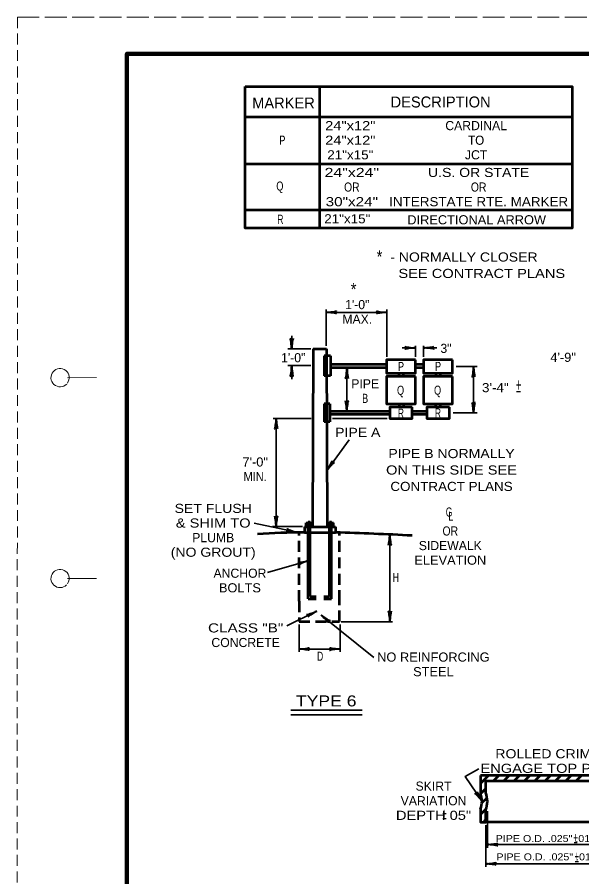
# Model space of a CAD drawing. Extents: x -209 to 471, y -242 to 199.
# Drawn here: x -208.7 to -54, y -37 to 198.5 of the extents above; entities that cross this region are included whole.
import ezdxf
from ezdxf.enums import TextEntityAlignment as Align

# ---------------------------------------------------------------- set-up
doc = ezdxf.new("R2010")
doc.units = 0
doc.linetypes.add('LONG_DASHED', pattern=[7.5, 6, -1.5])
doc.linetypes.add('MEDIUM_DASHED', pattern=[4.5, 3, -1.5])
doc.layers.add('1', color=7, linetype='Continuous', lineweight=53)
doc.layers.add('61', color=7, linetype='Continuous', lineweight=35)

msp = doc.modelspace()

# ---------------------------------------------------------------- linework, layer by layer
at = {"layer": '1', "linetype": 'MEDIUM_DASHED', "lineweight": 13}
msp.add_line((-208.646, 198.515), (-208.706, -241.525), dxfattribs=at)
at = {"layer": '1'}
for p, q in [((-125.758, 140.697), (-125.758, 179.502)), ((-146.273, 171.208), (-56.667, 171.208)), ((-146.273, 158.332), (-56.667, 158.332)), ((-146.273, 145.777), (-56.667, 145.777)), ((-127.607, 107.697), (-127.742, 58.912)), ((-127.607, 107.697), (-123.953, 107.697)), ((-123.953, 107.697), (-123.751, 58.912)), ((-122.877, 105.734), (-124.623, 105.734)), ((-124.623, 105.734), (-124.623, 100.233)), ((-122.877, 105.734), (-122.877, 100.233)), ((-107.531, 103.394), (-122.877, 103.394)), ((-107.531, 102.464), (-122.877, 102.464)), ((-97.371, 103.358), (-99.585, 103.358)), ((-97.371, 102.502), (-99.585, 102.502)), ((-122.877, 100.233), (-124.623, 100.233)), ((-104.015, 100.077), (-104.015, 101.011)), ((-102.83, 100.077), (-102.83, 101.011)), ((-93.855, 100.077), (-93.855, 101.011)), ((-92.67, 100.077), (-92.67, 101.011)), ((-123.036, 92.643), (-124.623, 92.643)), ((-124.623, 92.643), (-124.623, 87.642)), ((-123.036, 92.643), (-123.036, 87.642)), ((-104.015, 92.597), (-104.015, 91.661)), ((-102.83, 92.597), (-102.83, 91.661)), ((-93.988, 91.661), (-93.988, 92.597)), ((-92.697, 91.661), (-92.697, 92.597)), ((-106.595, 90.516), (-123.036, 90.516)), ((-106.595, 89.671), (-123.036, 89.671)), ((-96.435, 90.516), (-100.426, 90.516)), ((-96.435, 89.671), (-100.425, 89.671)), ((-123.036, 87.642), (-124.623, 87.642)), ((-130.005, 58.912), (-121.489, 58.912)), ((-130.005, 58.912), (-130.005, 57.361)), ((-129.473, 58.912), (-129.473, 59.977)), ((-129.473, 59.977), (-127.875, 59.977)), ((-129.02, 59.977), (-129.02, 60.056)), ((-129.02, 60.056), (-128.328, 60.056)), ((-128.94, 60.243), (-128.408, 60.243)), ((-128.94, 60.056), (-128.94, 60.243)), ((-128.94, 39.217), (-128.94, 59.977)), ((-128.408, 60.056), (-128.408, 60.243)), ((-128.408, 39.823), (-128.408, 59.977)), ((-128.328, 59.977), (-128.328, 60.056)), ((-127.875, 58.912), (-127.875, 59.977)), ((-123.618, 59.977), (-122.021, 59.977)), ((-123.618, 58.912), (-123.618, 59.977)), ((-123.166, 59.977), (-123.166, 60.056)), ((-123.166, 60.056), (-122.474, 60.056)), ((-123.086, 60.243), (-122.554, 60.243)), ((-123.086, 60.056), (-123.086, 60.243)), ((-123.086, 39.823), (-123.086, 59.977)), ((-122.554, 60.056), (-122.554, 60.243)), ((-122.554, 39.217), (-122.554, 59.977)), ((-122.474, 59.977), (-122.474, 60.056)), ((-122.021, 58.912), (-122.021, 59.977)), ((-121.489, 58.912), (-121.489, 57.361)), ((-130.005, 57.361), (-121.489, 57.361)), ((-128.94, 39.217), (-126.811, 39.217)), ((-128.408, 39.823), (-126.811, 39.823)), ((-124.681, 39.823), (-123.086, 39.823)), ((-124.681, 39.217), (-122.554, 39.217)), ((-81.745, -9.195), (-81.745, -14.242)), ((-81.745, -11.425), (-79.515, -9.195)), ((-78.151, -10.659), (-76.687, -9.195)), ((-75.322, -10.659), (-73.858, -9.195)), ((-72.494, -10.659), (-71.03, -9.195)), ((-69.665, -10.659), (-68.201, -9.195)), ((-66.837, -10.659), (-65.373, -9.195)), ((-64.009, -10.659), (-62.544, -9.195)), ((-61.18, -10.659), (-59.716, -9.195)), ((-58.352, -10.659), (-56.888, -9.195)), ((-55.523, -10.659), (-54.059, -9.195)), ((-81.742, -14.251), (-80.281, -12.79)), ((-81.359, -16.697), (-79.957, -15.294)), ((-81.745, -19.911), (-80.201, -18.366)), ((-80.963, -21.957), (-80.281, -21.275)), ((-46.185, -21.957), (-80.281, -21.957))]:
    msp.add_line(p, q, dxfattribs=at)
at = {"layer": '1', "lineweight": 35}
for p, q in [((-124.04, 108.496), (-124.04, 118.454)), ((-107.42, 105.457), (-107.42, 118.454)), ((-107.42, 117.655), (-124.04, 117.655)), ((-133.476, 111.224), (-133.476, 107.594)), ((-99.585, 105.457), (-99.585, 108.465)), ((-97.371, 105.457), (-97.371, 108.465)), ((-128.275, 107.697), (-134.506, 107.697)), ((-99.585, 107.935), (-103.215, 107.935)), ((-93.741, 107.935), (-97.371, 107.935)), ((-128.275, 103.095), (-134.506, 103.095)), ((-133.476, 102.996), (-133.476, 99.366)), ((-118.36, 102.464), (-118.36, 90.516)), ((-88.425, 102.835), (-82.646, 102.835)), ((-83.646, 102.835), (-83.646, 90.118)), ((-89.266, 90.118), (-82.646, 90.118)), ((-128.187, 88.596), (-138.514, 88.596)), ((-137.736, 88.596), (-137.736, 58.954)), ((-107.327, 88.596), (-122.31, 88.596)), ((-123.793, 74.388), (-117.719, 82.778)), ((-132.043, 57.415), (-143.764, 59.901)), ((-130.545, 58.954), (-138.705, 58.954)), ((-106.585, 32.92), (-106.585, 56.801)), ((-128.94, 49.597), (-140.112, 46.417)), ((-126.643, 35.808), (-134.791, 31.772)), ((-125.403, 34.721), (-110.972, 23.157)), ((-131.461, 32.148), (-131.461, 24.7)), ((-120.22, 32.126), (-120.22, 24.679)), ((-119.891, 32.92), (-105.859, 32.92)), ((-131.461, 25.427), (-120.22, 25.427)), ((-133.729, 8.726), (-114.169, 8.726)), ((-133.729, 7.361), (-114.169, 7.361)), ((-79.864, -18.944), (-79.864, -28.988)), ((-80.281, -22.836), (-80.281, -34.273)), ((-79.864, -28.109), (-46.599, -28.109)), ((-80.281, -33.395), (-46.185, -33.395))]:
    msp.add_line(p, q, dxfattribs=at)
at = {"layer": '1', "linetype": 'MEDIUM_DASHED'}
for p, q in [((-131.473, 38.541), (-131.473, 57.345)), ((-120.36, 38.541), (-120.36, 57.326))]:
    msp.add_line(p, q, dxfattribs=at)
at = {"layer": '1'}
for points in [[(-146.273, 179.502), (-56.667, 179.502), (-56.667, 140.697), (-146.273, 140.697)], [(-99.585, 104.658), (-107.531, 104.658), (-107.531, 101.011), (-99.585, 101.011)], [(-89.425, 104.658), (-97.371, 104.658), (-97.371, 101.011), (-89.425, 101.011)], [(-99.585, 100.077), (-107.531, 100.077), (-107.531, 92.597), (-99.585, 92.597)], [(-89.425, 100.077), (-97.371, 100.077), (-97.371, 92.597), (-89.425, 92.597)], [(-100.426, 91.661), (-106.595, 91.661), (-106.595, 88.575), (-100.426, 88.575)], [(-90.266, 91.661), (-96.435, 91.661), (-96.435, 88.575), (-90.266, 88.575)]]:
    msp.add_lwpolyline(points, close=True, dxfattribs=at)
at = {"layer": '1', "linetype": 'MEDIUM_DASHED'}
msp.add_lwpolyline([(-131.473, 38.541), (-131.473, 32.948), (-120.36, 32.948), (-120.36, 38.541)], dxfattribs=at)
msp.add_lwpolyline([(-131.473, 38.541), (-131.473, 32.948), (-120.36, 32.948), (-120.36, 38.541)], dxfattribs=at)
at = {"layer": '1', "lineweight": 35}
msp.add_lwpolyline([(-81.328, -16.308), (-85.959, -9.53), (-82.231, -7.366)], dxfattribs=at)
at = {"layer": '1'}
for points in [[(-44.721, -14.248), (-44.721, -9.195), (-81.745, -9.195)], [(-80.281, -13.966), (-80.281, -10.659), (-46.185, -10.659), (-46.185, -13.973)], [(-81.745, -18.375), (-81.745, -21.957), (-80.281, -21.957), (-80.281, -18.651)]]:
    msp.add_lwpolyline(points, dxfattribs=at)
for centre, radius, start, end in [((-127.954, -189.648), 247.017, 90.47573, 93.46734), ((-154.039, -1008.148), 1066.006, 87.12083, 88.25023), ((-86.666, -16.308), 6.801, 339.85367, 20.14633), ((-86.666, -16.308), 5.337, 337.22508, 22.77492)]:
    msp.add_arc(centre, radius, start, end, dxfattribs=at)
at = {"layer": '1', "lineweight": 40}
for centre, major_axis, ratio, start_param, end_param in [((-122.919, 117.867), (-1.756, -0.176), 0.07063, 0.8650754, 3.1424706), ((-108.511, 117.932), (1.786, -0.156), 0.122415, 3.1415927, 5.386832), ((-108.511, 117.932), (1.786, -0.156), 0.122415, 3.1415927, 5.386832), ((-122.949, 117.379), (-1.786, 0.156), 0.122415, 3.1415927, 5.386832), ((-108.541, 117.444), (1.756, 0.176), 0.07063, 0.8650754, 3.1424706), ((-108.541, 117.444), (1.756, 0.176), 0.07063, 0.8650754, 3.1424706), ((-133.688, 108.714), (0.176, -1.756), 0.07063, 0.8650754, 3.1424706), ((-133.2, 108.685), (-0.156, -1.786), 0.122415, 3.1415927, 5.386832), ((-100.676, 108.211), (1.786, -0.156), 0.122415, 3.1415927, 5.386832), ((-96.25, 108.146), (-1.756, -0.176), 0.07063, 0.8650754, 3.1424706), ((-100.705, 107.723), (1.756, 0.176), 0.07063, 0.8650754, 3.1424706), ((-96.28, 107.658), (-1.786, 0.156), 0.122415, 3.1415927, 5.386832), ((-133.752, 101.904), (0.156, 1.786), 0.122415, 3.1415927, 5.386832), ((-133.264, 101.875), (-0.176, 1.756), 0.07063, 0.8650754, 3.1424706), ((-118.628, 101.364), (0.156, 1.786), 0.122415, 3.1415927, 5.386832), ((-118.14, 101.335), (-0.176, 1.756), 0.07063, 0.8650754, 3.1424706), ((-83.923, 101.743), (0.156, 1.786), 0.122415, 3.1415927, 5.386832), ((-83.435, 101.714), (-0.176, 1.756), 0.07063, 0.8650754, 3.1424706), ((-118.58, 91.645), (0.176, -1.756), 0.07063, 0.8650754, 3.1424706), ((-118.092, 91.616), (-0.156, -1.786), 0.122415, 3.1415927, 5.386832), ((-83.858, 91.239), (0.176, -1.756), 0.07063, 0.8650754, 3.1424706), ((-83.37, 91.209), (-0.156, -1.786), 0.122415, 3.1415927, 5.386832), ((-138.012, 87.505), (0.156, 1.786), 0.122415, 3.1415927, 5.386832), ((-137.524, 87.475), (-0.176, 1.756), 0.07063, 0.8650754, 3.1424706), ((-123.307, 75.42), (-0.888, -1.526), 0.07063, 0.8650754, 3.1424706), ((-122.929, 75.11), (-1.174, -1.355), 0.122415, 3.1415927, 5.386832), ((-137.947, 60.075), (0.176, -1.756), 0.07063, 0.8650754, 3.1424706), ((-137.947, 60.075), (0.176, -1.756), 0.07063, 0.8650754, 3.1424706), ((-137.459, 60.046), (-0.156, -1.786), 0.122415, 3.1415927, 5.386832), ((-137.459, 60.046), (-0.156, -1.786), 0.122415, 3.1415927, 5.386832), ((-133.168, 57.371), (1.779, -0.218), 0.122415, 0.8963533, 3.1415927), ((-133.095, 57.854), (1.682, -0.536), 0.07063, 3.1407148, 5.41811), ((-106.797, 55.681), (0.176, 1.756), 0.07063, 3.1407148, 5.41811), ((-106.309, 55.71), (-0.156, 1.786), 0.122415, 0.8963533, 3.1415927), ((-130.076, 49.494), (1.737, 0.312), 0.07063, 3.1407148, 5.41811), ((-129.914, 49.032), (1.675, 0.639), 0.122415, 0.8963533, 3.1415927), ((-127.741, 35.5), (1.652, 0.622), 0.07063, 3.1407148, 5.41811), ((-127.741, 35.5), (1.652, 0.622), 0.07063, 3.1407148, 5.41811), ((-127.499, 35.076), (1.531, 0.932), 0.122415, 0.8963533, 3.1415927), ((-127.499, 35.076), (1.531, 0.932), 0.122415, 0.8963533, 3.1415927), ((-106.861, 34.011), (0.156, -1.786), 0.122415, 0.8963533, 3.1415927), ((-106.374, 34.04), (-0.176, -1.756), 0.07063, 3.1407148, 5.41811), ((-124.661, 33.855), (-1.261, 1.235), 0.07063, 3.1407148, 5.41811), ((-124.379, 34.254), (-1.491, 0.995), 0.122415, 0.8963533, 3.1415927), ((-130.341, 25.215), (-1.756, 0.176), 0.07063, 3.1407148, 5.41811), ((-130.341, 25.215), (-1.756, 0.176), 0.07063, 3.1407148, 5.41811), ((-130.37, 25.703), (-1.786, -0.156), 0.122415, 0.8963533, 3.1415927), ((-130.37, 25.703), (-1.786, -0.156), 0.122415, 0.8963533, 3.1415927), ((-121.311, 25.15), (1.786, 0.156), 0.122415, 0.8963533, 3.1415927), ((-121.311, 25.15), (1.786, 0.156), 0.122415, 0.8963533, 3.1415927), ((-121.341, 25.638), (1.756, -0.176), 0.07063, 3.1407148, 5.41811), ((-121.341, 25.638), (1.756, -0.176), 0.07063, 3.1407148, 5.41811), ((-82.172, -15.563), (1.136, -1.386), 0.122415, 0.8963533, 3.1415927), ((-82.172, -15.563), (1.136, -1.386), 0.122415, 0.8963533, 3.1415927), ((-81.785, -15.264), (0.846, -1.549), 0.07063, 3.1407148, 5.41811), ((-81.785, -15.264), (0.846, -1.549), 0.07063, 3.1407148, 5.41811), ((-78.773, -27.833), (-1.786, -0.156), 0.122415, 0.8963533, 3.1415927), ((-78.773, -27.833), (-1.786, -0.156), 0.122415, 0.8963533, 3.1415927), ((-78.743, -28.321), (-1.756, 0.176), 0.07063, 3.1407148, 5.41811), ((-78.743, -28.321), (-1.756, 0.176), 0.07063, 3.1407148, 5.41811), ((-79.19, -33.118), (-1.786, -0.156), 0.122415, 0.8963533, 3.1415927), ((-79.19, -33.118), (-1.786, -0.156), 0.122415, 0.8963533, 3.1415927), ((-79.161, -33.606), (-1.756, 0.176), 0.07063, 3.1407148, 5.41811), ((-79.161, -33.606), (-1.756, 0.176), 0.07063, 3.1407148, 5.41811)]:
    msp.add_ellipse(centre, major_axis=major_axis, ratio=ratio, start_param=start_param, end_param=end_param, dxfattribs=at)
at = {"layer": '61', "linetype": 'LONG_DASHED', "lineweight": 13}
msp.add_line((-208.646, 198.515), (471.374, 198.515), dxfattribs=at)
at = {"layer": '61', "lineweight": 13}
for p, q in [((-194.926, 99.755), (-186.946, 99.775)), ((-194.946, 44.755), (-186.946, 44.755))]:
    msp.add_line(p, q, dxfattribs=at)
at = {"layer": '61', "lineweight": 158}
msp.add_lwpolyline([(460.394, 188.515), (-178.646, 188.515), (-178.646, -231.505)], dxfattribs=at)
at = {"layer": '61', "lineweight": 13}
for centre, end in [((-196.948, 99.756), 316.23216), ((-196.948, 44.756), 315.37577)]:
    msp.add_arc(centre, 2.5, 323.13009, end, dxfattribs=at)

# ---------------------------------------------------------------- texts
at = {"layer": '1'}
for s, p in [('DESCRIPTION', (-106.384, 173.785)), ('MARKER', (-144.314, 173.509))]:
    msp.add_text(s, height=3, dxfattribs=at).set_placement(p)
for s, height, width, p in [('24"x12"', 2.5, 1.2, (-117.418, 167.567)), ('P', 2.5, 0.75, (-136.038, 163.567)), ('24"x12"', 2.5, 1.2, (-117.418, 163.567)), ('TO', 2.5, 0.95, (-82.936, 163.567)), ('21"x15"', 2.5, 1.1, (-117.418, 159.567)), ('24"x24"', 2.5, 1.3, (-117.004, 154.735)), ('U.S. OR STATE', 2.5, 1.15, (-82.246, 154.735)), ('Q', 2.5, 0.75, (-136.728, 151.011)), ('OR', 2.5, 0.85, (-117.004, 150.735)), ('OR', 2.5, 0.85, (-82.246, 150.735)), ('30"x24"', 2.5, 1.25, (-117.004, 146.735)), ('INTERSTATE RTE. MARKER', 2.5, 1.1, (-82.247, 146.735)), ('R', 2.5, 0.7, (-136.59, 141.905)), ('21"x15"', 2.5, 1.1, (-118.245, 142.043)), ('DIRECTIONAL ARROW', 2.5, 1.05, (-82.798, 141.767)), ('*', 3.5, 0.85, (-109.41, 131.146)), ('*', 3.5, 0.85, (-116.516, 122.229)), ('4\'-9"', 2.5, 1.05, (-59.108, 104.094)), ('P', 2.5, 0.75, (-103.526, 101.576)), ('P', 2.5, 0.75, (-93.38, 101.605)), ('+', 3.5, 0.55, (-71.311, 96.062)), ('Q', 2.5, 0.75, (-103.642, 95.061)), ('Q', 2.5, 0.75, (-93.496, 95.09)), ('3\'-4"', 2.5, 1.1, (-77.673, 95.791)), ('B', 2.5, 0.75, (-113.355, 92.849)), ('R', 2.5, 0.7, (-103.555, 88.809)), ('R', 2.5, 0.7, (-93.409, 88.838)), ('PIPE A', 2.5, 1.15, (-115.373, 83.534)), ('PIPE B NORMALLY', 2.5, 1.15, (-89.684, 77.726)), ('7\'-0"', 2.5, 1.05, (-143.489, 75.425)), ('ON THIS SIDE SEE', 2.5, 1.2, (-89.684, 73.226)), ('MIN.', 2.5, 0.9, (-143.489, 71.425)), ('CONTRACT PLANS', 2.5, 1.1, (-89.684, 68.726)), ('SET FLUSH', 2.5, 1.15, (-154.99, 62.704)), ('G', 2.5, 0.7, (-90.362, 61.715)), ('& SHIM TO', 2.5, 1.2, (-154.99, 58.704)), ('L', 2.5, 0.75, (-89.876, 60.579)), ('OR', 2.5, 0.85, (-90.019, 56.526)), ('(NO GROUT)', 2.5, 1.15, (-154.99, 50.704)), ('ELEVATION', 2.5, 1.05, (-90.019, 48.526)), ('H', 2.5, 0.7, (-104.946, 43.777)), ('BOLTS', 2.5, 1.05, (-147.665, 40.954)), ('CLASS "B"', 2.5, 1.25, (-146.101, 29.969)), ('D', 2.5, 0.7, (-125.688, 22.206)), ('NO REINFORCING', 2.5, 1.05, (-94.658, 21.983)), ('STEEL', 2.5, 1.05, (-94.658, 17.983)), ('ROLLED CRIMP TO', 2.5, 1.15, (-60.049, -4.497)), ('ENGAGE TOP PIPE "A"', 2.5, 1.2, (-60.049, -8.497)), ('DEPTH 05"', 2.5, 1.2, (-94.611, -21.373)), ('+', 3, 0.55, (-91.6, -21.104)), ('PIPE O.D. .025" .010"', 1.9, 1.15, (-63.303, -27.43)), ('+', 3, 0.55, (-55.667, -27.73)), ('PIPE O.D. .025" .010"', 1.9, 1.15, (-63.102, -32.45)), ('+', 3, 0.55, (-55.333, -32.884))]:
    msp.add_text(s, height=height, dxfattribs=dict(at, width=width)).set_placement(p, align=Align.CENTER)
for s, height, p in [('CARDINAL', 2.5, (-82.936, 167.567)), ('JCT', 2.5, (-82.936, 159.567)), ('1\'-0"', 2.5, (-115.516, 118.534)), ('MAX.', 2.5, (-115.516, 114.534)), ('3"', 2.5, (-91.207, 106.538)), ('1\'-0"', 2.5, (-133.059, 103.991)), ('PIPE', 2.5, (-113.355, 96.849)), ('-', 3.5, (-71.311, 94.592)), ('PLUMB', 2.5, (-154.99, 54.704)), ('SIDEWALK', 2.5, (-90.019, 52.526)), ('ANCHOR', 2.5, (-147.665, 44.954)), ('CONCRETE', 2.5, (-146.101, 25.969)), ('SKIRT', 2.5, (-94.611, -13.373)), ('VARIATION', 2.5, (-94.611, -17.373)), ('-', 3, (-91.6, -22.175)), ('-', 3, (-55.667, -28.801)), ('-', 3, (-55.333, -33.955))]:
    msp.add_text(s, height=height, dxfattribs=at).set_placement(p, align=Align.CENTER)
for s, height, width, p in [('- NORMALLY CLOSER', 2.5, 1.15, (-106.471, 131.572)), ('  SEE CONTRACT PLANS', 2.5, 1.2, (-106.471, 127.072)), ('TYPE 6', 3, 1.2, (-132.315, 9.722))]:
    msp.add_text(s, height=height, dxfattribs=dict(at, width=width)).set_placement(p)

doc.saveas('drawing.dxf')
